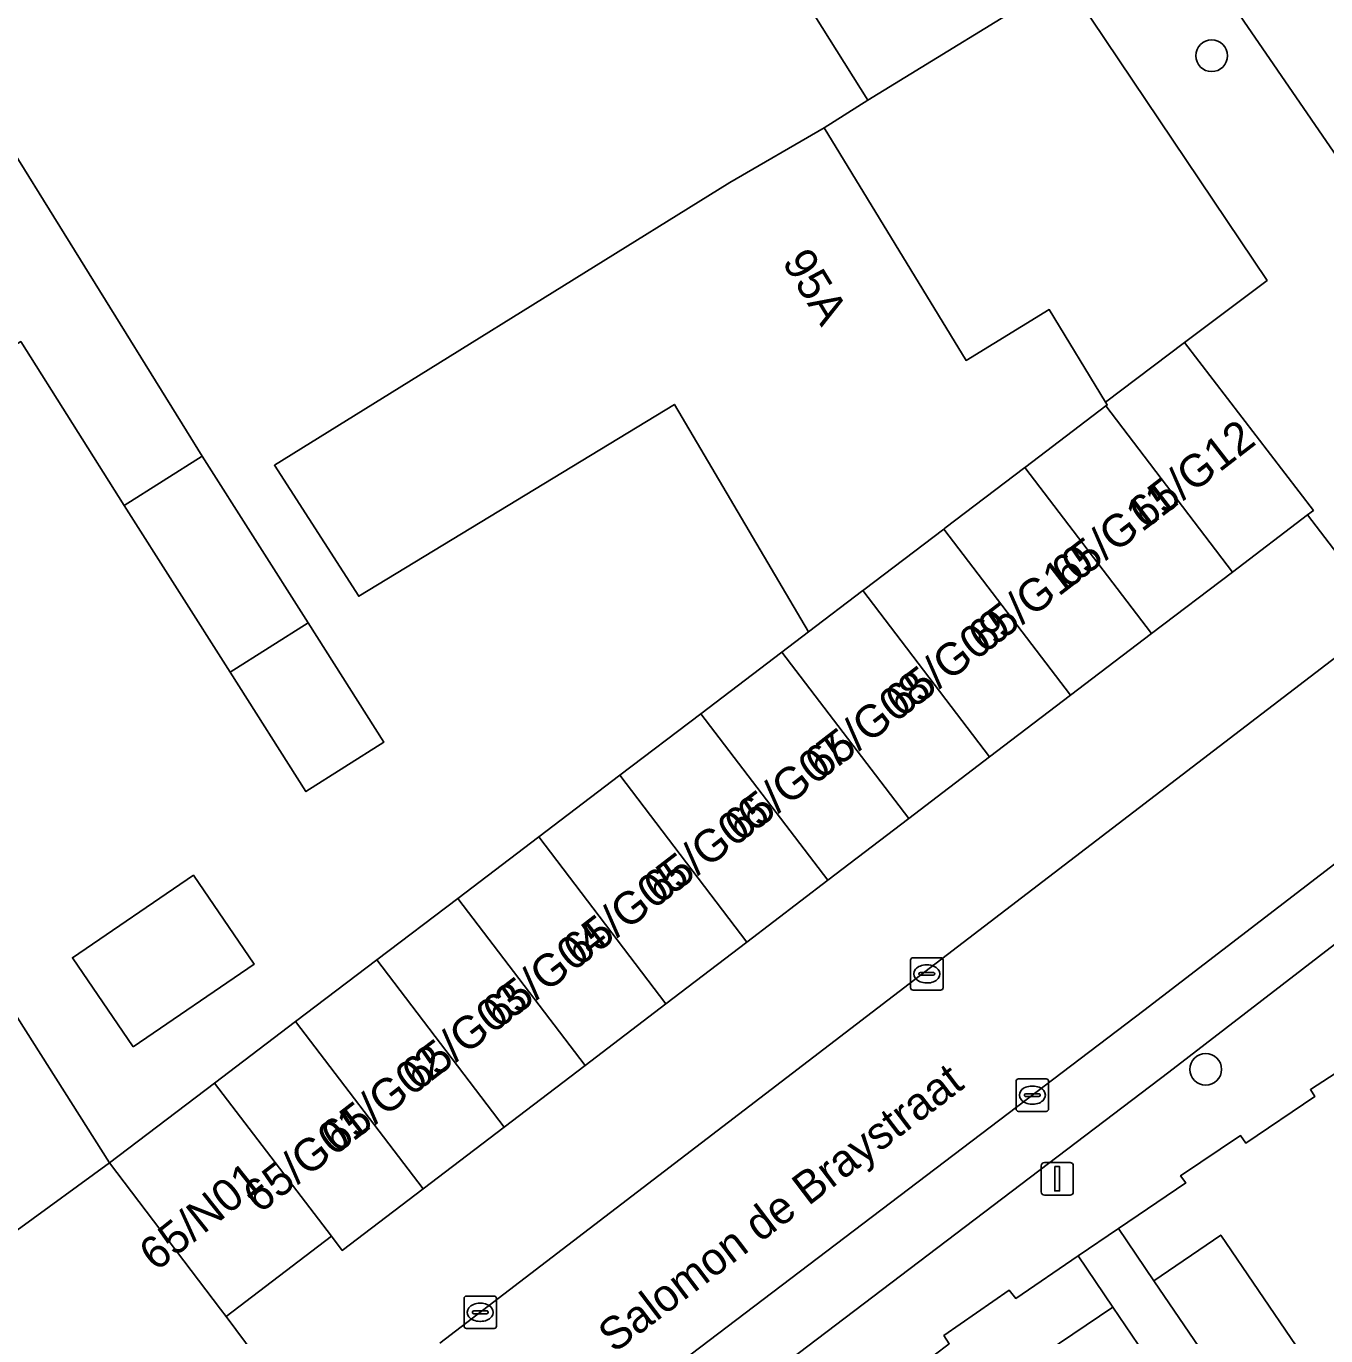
# Model space of a CAD drawing. Extents: x 159664 to 160323, y 385312 to 386115.
# Drawn here: x 159994.02 to 160034.06, y 386033.62 to 386073.99 of the extents above; entities that cross this region are included whole.
import ezdxf

# ---------------------------------------------------------------- set-up
doc = ezdxf.new("R2010")
doc.units = 0
for name, color, linetype in [('IMGEO_Boom', 7, 'Continuous'), ('IMGEO_Erf', 7, 'Continuous'), ('IMGEO_Fietspad_gesloten', 7, 'Continuous'), ('IMGEO_Kolk', 7, 'Continuous'), ('IMGEO_Lichtmast', 7, 'Continuous'), ('IMGEO_Muur', 7, 'Continuous'), ('IMGEO_Openbare_ruimte_label', 7, 'Continuous'), ('IMGEO_Pand', 7, 'Continuous'), ('IMGEO_Pand_nummerreeks', 7, 'Continuous'), ('IMGEO_Parkeervlak_open', 7, 'Continuous'), ('IMGEO_Rijbaan_lokaal_open', 7, 'Continuous'), ('IMGEO_Voetpad_open', 7, 'Continuous')]:
    doc.layers.add(name, color=color, linetype=linetype)

msp = doc.modelspace()

# ---------------------------------------------------------------- linework, layer by layer
at = {"layer": 'IMGEO_Boom'}
for centre in [(160030.544, 386073.077), (160030.363, 386041.831)]:
    msp.add_circle(centre, 0.489, dxfattribs=at)
at = {"layer": 'IMGEO_Erf'}
for points in [[(159987.446, 386053.348), (159996.585, 386038.952), (159999.819, 386041.409), (160002.318, 386043.308), (160004.815, 386045.205), (160007.311, 386047.102), (160009.808, 386049), (160012.304, 386050.897), (160014.801, 386052.794), (160017.298, 386054.691), (160018.121, 386055.317), (160013.989, 386062.33), (160004.262, 386056.418), (160001.662, 386060.453), (160006.104, 386063.213), (160015.693, 386069.17), (160018.609, 386070.859), (160019.954, 386071.713), (160009.767, 386087.924), (159990.068, 386075.84)], [(159992.679, 386071.631), (159998.951, 386061.51), (159999.44, 386060.734), (160002.702, 386055.6), (160005.039, 386051.922), (160002.633, 386050.393), (160000.296, 386054.071), (159997.029, 386059.214), (159993.845, 386064.265)], [(160042.354, 386032.388), (160038.98, 386037.361), (160037.639, 386036.449), (160035.865, 386039.062), (160037.207, 386039.973), (160035.517, 386042.461), (160033.587, 386041.205), (160033.727, 386040.995), (160031.597, 386039.558), (160031.437, 386039.788), (160029.587, 386038.552), (160029.747, 386038.332), (160027.671, 386036.921), (160028.763, 386035.316), (160030.825, 386036.72), (160033.146, 386033.31)], [(160025.449, 386033.112), (160027.504, 386034.499), (160026.431, 386036.077), (160024.507, 386034.77), (160024.307, 386035.02), (160022.297, 386033.623), (160022.457, 386033.373)]]:
    msp.add_lwpolyline(points, dxfattribs=at)
msp.add_lwpolyline([(159997.312, 386042.526), (159995.44, 386045.27), (159999.166, 386047.813), (160001.038, 386045.069)], close=True, dxfattribs=at)
at = {"layer": 'IMGEO_Fietspad_gesloten'}
msp.add_lwpolyline([(160019.602, 386088.23), (160021.107, 386086.925), (160023.91, 386084.079), (160027.277, 386080.36), (160034.647, 386069.613), (160036.811, 386066.205), (160038.328, 386063.633), (160039.436, 386061.981), (160045.694, 386052.822), (160114.376, 385951.813), (160120.736, 385942.537), (160142.935, 385909.961), (160144.932, 385911.316), (160142.024, 385915.62), (160129.151, 385934.503)], dxfattribs=at)
at = {"layer": 'IMGEO_Kolk'}
for p, q in [((160021.267, 386044.347), (160021.267, 386045.199)), ((160021.342, 386045.273), (160022.194, 386045.273)), ((160022.268, 386045.199), (160022.268, 386044.347)), ((160021.526, 386044.767), (160021.526, 386044.779)), ((160021.569, 386044.816), (160021.967, 386044.816)), ((160021.755, 386045.053), (160021.78, 386045.053)), ((160022.01, 386044.779), (160022.01, 386044.767)), ((160021.964, 386044.73), (160021.566, 386044.73)), ((160021.778, 386044.493), (160021.753, 386044.493)), ((160022.194, 386044.273), (160021.342, 386044.273)), ((160024.594, 386041.536), (160025.446, 386041.536)), ((160024.519, 386040.61), (160024.519, 386041.462)), ((160025.007, 386041.316), (160025.032, 386041.316)), ((160025.52, 386041.462), (160025.52, 386040.61)), ((160024.778, 386041.03), (160024.778, 386041.042)), ((160025.216, 386040.993), (160024.818, 386040.993)), ((160024.821, 386041.079), (160025.219, 386041.079)), ((160025.03, 386040.756), (160025.005, 386040.756)), ((160025.262, 386041.042), (160025.262, 386041.03)), ((160025.446, 386040.536), (160024.594, 386040.536)), ((160007.506, 386033.915), (160007.506, 386034.767)), ((160007.581, 386034.841), (160008.433, 386034.841)), ((160008.507, 386034.767), (160008.507, 386033.915)), ((160007.765, 386034.335), (160007.765, 386034.347)), ((160008.203, 386034.298), (160007.805, 386034.298)), ((160007.808, 386034.384), (160008.206, 386034.384)), ((160007.994, 386034.621), (160008.019, 386034.621)), ((160008.249, 386034.347), (160008.249, 386034.335)), ((160008.017, 386034.061), (160007.992, 386034.061)), ((160008.433, 386033.841), (160007.581, 386033.841))]:
    msp.add_line(p, q, dxfattribs=at)
for points in [[(160021.267, 386044.347), (160021.267, 386045.199)], [(160021.342, 386045.273), (160022.194, 386045.273)], [(160022.268, 386045.199), (160022.268, 386044.347)], [(160022.194, 386044.273), (160021.342, 386044.273)], [(160024.594, 386041.536), (160025.446, 386041.536)], [(160024.519, 386040.61), (160024.519, 386041.462)], [(160025.52, 386041.462), (160025.52, 386040.61)], [(160025.446, 386040.536), (160024.594, 386040.536)], [(160007.506, 386033.915), (160007.506, 386034.767)], [(160007.581, 386034.841), (160008.433, 386034.841)], [(160008.507, 386034.767), (160008.507, 386033.915)], [(160008.433, 386033.841), (160007.581, 386033.841)]]:
    msp.add_lwpolyline(points, dxfattribs=at)
for centre, radius, start, end in [((160021.344, 386045.197), 0.0765, 91.552, 178.448), ((160021.344, 386045.197), 0.0765, 91.552, 178.448), ((160022.192, 386045.197), 0.0765, 1.552, 88.448), ((160022.192, 386045.197), 0.0765, 1.552, 88.448), ((160021.566, 386044.776), 0.0403, 85.8775, 175.7526), ((160021.563, 386044.766), 0.0366, 178.938, 274.7102), ((160021.967, 386044.773), 0.043, 264.8664, 352.4533), ((160021.971, 386044.778), 0.0386, 1.7309, 96.639), ((160021.344, 386044.349), 0.0765, 181.552, 268.448), ((160021.344, 386044.349), 0.0765, 181.552, 268.448), ((160022.192, 386044.349), 0.0765, 271.552, 358.448), ((160022.192, 386044.349), 0.0765, 271.552, 358.448), ((160024.596, 386041.46), 0.0765, 91.552, 178.448), ((160024.596, 386041.46), 0.0765, 91.552, 178.448), ((160025.444, 386041.46), 0.0765, 1.552, 88.448), ((160025.444, 386041.46), 0.0765, 1.552, 88.448), ((160024.818, 386041.039), 0.0403, 85.8775, 175.7526), ((160024.815, 386041.029), 0.0366, 178.938, 274.7102), ((160025.219, 386041.036), 0.043, 264.8664, 352.4533), ((160025.223, 386041.041), 0.0386, 1.7309, 96.639), ((160024.596, 386040.612), 0.0765, 181.552, 268.448), ((160024.596, 386040.612), 0.0765, 181.552, 268.448), ((160025.444, 386040.612), 0.0765, 271.552, 358.448), ((160025.444, 386040.612), 0.0765, 271.552, 358.448), ((160007.583, 386034.765), 0.0765, 91.552, 178.448), ((160007.583, 386034.765), 0.0765, 91.552, 178.448), ((160008.431, 386034.765), 0.0765, 1.552, 88.448), ((160008.431, 386034.765), 0.0765, 1.552, 88.448), ((160007.805, 386034.344), 0.0403, 85.8775, 175.7526), ((160007.802, 386034.334), 0.0366, 178.938, 274.7102), ((160008.206, 386034.341), 0.043, 264.8664, 352.4533), ((160008.21, 386034.346), 0.0386, 1.7309, 96.639), ((160007.583, 386033.917), 0.0765, 181.552, 268.448), ((160007.583, 386033.917), 0.0765, 181.552, 268.448), ((160008.431, 386033.917), 0.0765, 271.552, 358.448), ((160008.431, 386033.917), 0.0765, 271.552, 358.448)]:
    msp.add_arc(centre, radius, start, end, dxfattribs=at)
for centre, major_axis, ratio, start_param, end_param in [((160021.754, 386044.773), (-0.387, 0.002), 0.722429, 4.712389, 7.853982), ((160021.779, 386044.773), (-0.39, 0.002), 0.717154, 1.570796, 4.712389), ((160025.006, 386041.036), (-0.387, 0.002), 0.722429, 4.712389, 7.853982), ((160025.031, 386041.036), (-0.39, 0.002), 0.717154, 1.570796, 4.712389), ((160007.993, 386034.341), (-0.387, 0.002), 0.722429, 4.712389, 7.853982), ((160008.018, 386034.341), (-0.39, 0.002), 0.717154, 1.570796, 4.712389)]:
    msp.add_ellipse(centre, major_axis=major_axis, ratio=ratio, start_param=start_param, end_param=end_param, dxfattribs=at)
at = {"layer": 'IMGEO_Lichtmast'}
for p, q in [((160025.291, 386038.056), (160025.291, 386038.856)), ((160025.291, 386038.856), (160025.291, 386038.056)), ((160025.391, 386038.956), (160026.181, 386038.956)), ((160026.181, 386038.956), (160025.391, 386038.956)), ((160026.281, 386038.856), (160026.281, 386038.056)), ((160026.281, 386038.056), (160026.281, 386038.856)), ((160026.181, 386037.956), (160025.391, 386037.956)), ((160025.391, 386037.956), (160026.181, 386037.956))]:
    msp.add_line(p, q, dxfattribs=at)
msp.add_lwpolyline([(160025.711, 386038.831), (160025.861, 386038.831), (160025.861, 386038.081), (160025.711, 386038.081), (160025.711, 386038.831)], dxfattribs=at)
for centre, start, end in [((160025.391, 386038.856), 90, 180), ((160025.391, 386038.856), 90, 180), ((160026.181, 386038.856), 0, 90), ((160026.181, 386038.856), 360, 90), ((160025.391, 386038.056), 180, 270), ((160025.391, 386038.056), 180, 270), ((160026.181, 386038.056), 270, 0), ((160026.181, 386038.056), 270, 0)]:
    msp.add_arc(centre, 0.1, start, end, dxfattribs=at)
at = {"layer": 'IMGEO_Muur'}
for points in [[(159996.585, 386038.952), (159987.446, 386053.348)], [(160027.671, 386036.921), (160029.747, 386038.332), (160029.587, 386038.552), (160031.437, 386039.788), (160031.597, 386039.558), (160033.727, 386040.995), (160033.587, 386041.205), (160035.517, 386042.461)], [(160026.436, 386036.081), (160024.507, 386034.77), (160024.307, 386035.02), (160022.297, 386033.623), (160022.457, 386033.373), (160020.607, 386031.976), (160020.277, 386032.137), (160018.415, 386030.873)]]:
    msp.add_lwpolyline(points, dxfattribs=at)
at = {"layer": 'IMGEO_Pand'}
for points in [[(159999.44, 386060.734), (159998.951, 386061.51), (159992.679, 386071.631), (159990.696, 386070.404), (159989.928, 386071.634), (159985.906, 386069.124), (159990.297, 386062.06), (159993.845, 386064.265), (159997.029, 386059.214)], [(160006.104, 386063.213), (160001.662, 386060.453), (160004.262, 386056.418), (160013.989, 386062.33), (160018.121, 386055.317), (160019.794, 386056.589), (160019.827, 386056.614), (160022.291, 386058.486), (160022.322, 386058.51), (160024.787, 386060.383), (160024.817, 386060.406), (160027.284, 386062.281), (160027.33, 386062.316), (160027.278, 386062.402), (160025.538, 386065.253), (160022.98, 386063.686), (160018.609, 386070.859), (160015.693, 386069.17)], [(160033.679, 386059.064), (160029.711, 386064.242), (160027.278, 386062.402), (160027.33, 386062.316), (160027.284, 386062.281), (160031.185, 386057.163), (160033.501, 386058.928)], [(160028.692, 386055.262), (160031.185, 386057.163), (160027.284, 386062.281), (160024.817, 386060.406), (160024.787, 386060.383)], [(159997.029, 386059.214), (160000.296, 386054.071), (160002.702, 386055.6), (159999.44, 386060.734)], [(160024.787, 386060.383), (160022.322, 386058.51), (160022.291, 386058.486), (160026.198, 386053.361), (160028.692, 386055.262)], [(160022.291, 386058.486), (160019.827, 386056.614), (160019.794, 386056.589), (160023.704, 386051.46), (160026.198, 386053.361)], [(160021.211, 386049.559), (160023.704, 386051.46), (160019.794, 386056.589), (160018.121, 386055.317), (160017.298, 386054.691)], [(160002.702, 386055.6), (160000.296, 386054.071), (160002.633, 386050.393), (160005.039, 386051.922)], [(160017.298, 386054.691), (160014.801, 386052.794), (160018.717, 386047.658), (160021.211, 386049.559)], [(160014.801, 386052.794), (160012.304, 386050.897), (160016.223, 386045.756), (160018.717, 386047.658)], [(160013.73, 386043.855), (160016.223, 386045.756), (160012.304, 386050.897), (160009.808, 386049)], [(160009.808, 386049), (160007.311, 386047.102), (160011.236, 386041.954), (160013.73, 386043.855)], [(159997.312, 386042.526), (160001.038, 386045.069), (159999.166, 386047.813), (159995.44, 386045.27)], [(160008.742, 386040.053), (160011.236, 386041.954), (160007.311, 386047.102), (160004.815, 386045.205)], [(160004.815, 386045.205), (160002.318, 386043.308), (160006.249, 386038.152), (160008.742, 386040.053)], [(160003.426, 386036.684), (160003.755, 386036.251), (160006.249, 386038.152), (160002.318, 386043.308), (159999.819, 386041.409)], [(159996.585, 386038.952), (160000, 386034.437), (160000.172, 386034.211), (160003.426, 386036.684), (159999.819, 386041.409)], [(160033.146, 386033.31), (160030.825, 386036.72), (160028.763, 386035.316), (160031.097, 386031.887)], [(160027.504, 386034.499), (160025.449, 386033.112), (160027.769, 386029.675), (160029.837, 386031.043)]]:
    msp.add_lwpolyline(points, close=True, dxfattribs=at)
at = {"layer": 'IMGEO_Parkeervlak_open'}
msp.add_lwpolyline([(160029.711, 386064.242), (160032.253, 386066.151), (160026.016, 386075.441), (160019.954, 386071.713), (160018.609, 386070.859), (160022.98, 386063.686), (160025.538, 386065.253), (160027.278, 386062.402)], close=True, dxfattribs=at)
msp.add_lwpolyline([(160013.539, 386029.833), (160029.23, 386041.746), (160040.331, 386050.301), (160040.231, 386050.418), (160040.141, 386050.545), (160040.063, 386050.678), (160039.996, 386050.818), (160039.942, 386050.963), (160039.9, 386051.112), (160039.871, 386051.264), (160039.856, 386051.418), (160039.854, 386051.572), (160039.865, 386051.727), (160039.889, 386051.879), (160039.927, 386052.029), (160039.977, 386052.176), (160040.04, 386052.317), (160040.115, 386052.453), (160040.201, 386052.581), (160040.298, 386052.702), (160040.404, 386052.814), (160039.915, 386052.454), (160028.451, 386043.642), (160011.991, 386031.144)], dxfattribs=at)
at = {"layer": 'IMGEO_Rijbaan_lokaal_open'}
for points in [[(160039.033, 386058.354), (160037.768, 386057.157), (160037.526, 386056.949), (160006.757, 386033.392)], [(160011.991, 386031.144), (160028.451, 386043.642), (160039.915, 386052.454), (160040.404, 386052.814), (160040.966, 386053.308), (160041.184, 386053.483)]]:
    msp.add_lwpolyline(points, dxfattribs=at)
at = {"layer": 'IMGEO_Voetpad_open'}
for points in [[(160015.058, 386090.116), (160013.717, 386090.142), (160009.172, 386089.922), (160009.767, 386087.924), (160019.954, 386071.713), (160026.016, 386075.441), (160032.253, 386066.151), (160029.711, 386064.242), (160033.679, 386059.064), (160033.501, 386058.928), (160034.964, 386057.001)], [(160039.436, 386061.981), (160038.328, 386063.633), (160036.811, 386066.205), (160034.647, 386069.613), (160027.277, 386080.36)], [(160034.964, 386057.001), (160033.501, 386058.928), (160031.185, 386057.163), (160028.692, 386055.262), (160026.198, 386053.361), (160023.704, 386051.46), (160021.211, 386049.559), (160018.717, 386047.658), (160016.223, 386045.756), (160013.73, 386043.855), (160011.236, 386041.954), (160008.742, 386040.053), (160006.249, 386038.152), (160003.755, 386036.251), (160003.426, 386036.684), (160000.172, 386034.211), (160003.096, 386030.288)], [(160006.757, 386033.392), (160037.526, 386056.949)], [(160040.331, 386050.301), (160029.23, 386041.746), (160013.539, 386029.833)], [(160022.457, 386033.373), (160022.297, 386033.623), (160024.307, 386035.02), (160024.507, 386034.77), (160026.431, 386036.077), (160026.436, 386036.081), (160027.671, 386036.921), (160029.747, 386038.332), (160029.587, 386038.552), (160031.437, 386039.788), (160031.597, 386039.558), (160033.727, 386040.995), (160033.587, 386041.205), (160035.517, 386042.461)], [(160003.096, 386030.288), (160000.172, 386034.211), (160000, 386034.437), (159996.585, 386038.952), (159993.737, 386036.877), (159989.606, 386033.897), (159990.855, 386032.064), (160000, 386018.644), (160012.705, 386000), (160014.692, 385997.067), (160015.814, 385995.41), (160049.629, 385945.494), (160050.759, 385943.825), (160071.141, 385913.737), (160067.916, 385911.581), (160069.413, 385909.399), (160091.367, 385923.112)], [(160031.097, 386031.887), (160028.763, 386035.316), (160027.671, 386036.921), (160026.436, 386036.081), (160026.431, 386036.077), (160027.504, 386034.499), (160029.837, 386031.043)]]:
    msp.add_lwpolyline(points, dxfattribs=at)
msp.add_lwpolyline([(159980.729, 386064.18), (159978.127, 386068.403), (159969.62, 386063.101), (159972.264, 386058.902), (159978.954, 386048.12), (159982.613, 386042.411), (159983.858, 386043.194), (159986, 386044.539), (159988.156, 386045.864), (159989.762, 386043.276), (159993.737, 386036.877), (159996.585, 386038.952), (159987.446, 386053.348), (159986.188, 386055.396)], close=True, dxfattribs=at)

# ---------------------------------------------------------------- texts
at = {"layer": 'IMGEO_Openbare_ruimte_label'}
msp.add_text('Salomon de Braystraat', height=1, rotation=37.202, dxfattribs=at).set_placement((160012.135, 386033.064))
at = {"layer": 'IMGEO_Pand_nummerreeks'}
for s, rotation, p in [('95A', 301.3568, (160017.288, 386066.724)), ('65/G12', 37.6942, (160028.492, 386058.449)), ('65/G11', 37.6942, (160026.102, 386056.602)), ('65/G10', 37.6942, (160023.534, 386054.618)), ('65/G09', 37.6942, (160020.974, 386052.64)), ('65/G08', 37.6942, (160018.497, 386050.726)), ('65/G07', 37.6942, (160016.012, 386048.805)), ('65/G06', 37.6942, (160013.529, 386046.887)), ('65/G05', 37.6942, (160011.046, 386044.969)), ('65/G04', 37.6942, (160008.564, 386043.05)), ('65/G03', 37.6942, (160006.081, 386041.132)), ('65/G02', 37.6942, (160003.593, 386039.21)), ('65/G01', 37.6942, (160001.203, 386037.362)), ('65/N01', 38.4181, (159998.012, 386035.577))]:
    msp.add_text(s, height=1, rotation=rotation, dxfattribs=at).set_placement(p)

doc.saveas('drawing.dxf')
